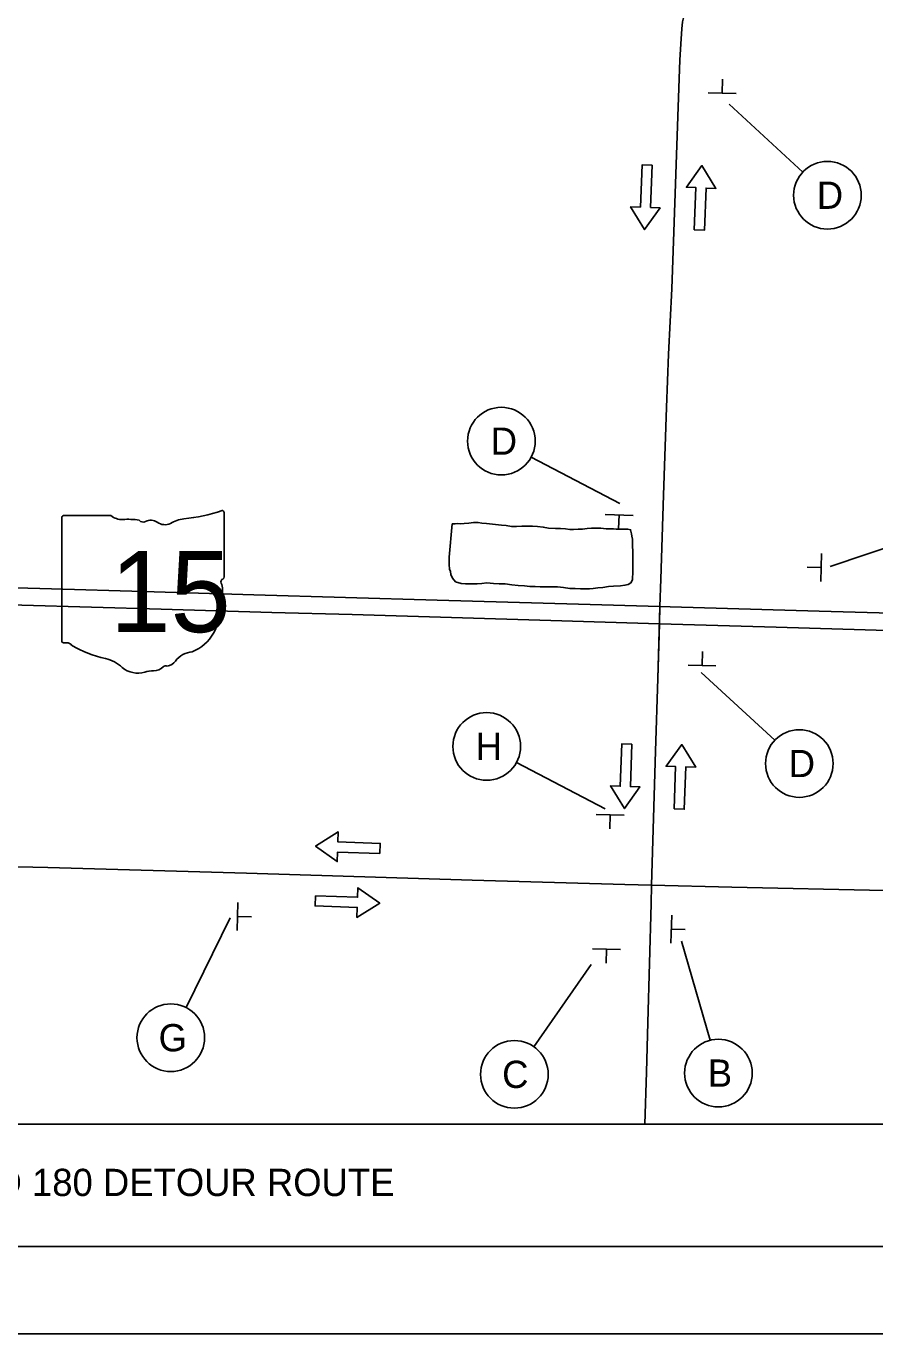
# Model space of a CAD drawing. Extents: x 1651.5 to 1685.5, y 1084.6 to 1106.6.
# Drawn here: x 1660.95 to 1665.81, y 1084.6 to 1092.09 of the extents above; entities that cross this region are included whole.
import ezdxf

# ---------------------------------------------------------------- set-up
doc = ezdxf.new("R2010")
doc.units = 0
for name, color, linetype in [('GM_X_County_Road', 7, 'Continuous'), ('GM_X_Minor_Lake', 7, 'Continuous'), ('GM_X_State_Route', 7, 'Continuous'), ('GM_X_State_Shield', 7, 'Continuous'), ('SC_Scratch1', 7, 'Continuous'), ('SH_Border', 7, 'Continuous'), ('SH_Data', 7, 'Continuous'), ('SH_Text', 7, 'Continuous'), ('SN_P_Signs', 7, 'Continuous')]:
    doc.layers.add(name, color=color, linetype=linetype)

msp = doc.modelspace()

# ---------------------------------------------------------------- linework, layer by layer
at = {"layer": 'GM_X_County_Road'}
for points in [[(1664.5833, 1088.7638), (1664.5876, 1088.9203), (1664.6035, 1089.4012), (1664.6207, 1089.904), (1664.6327, 1090.2091), (1664.6503, 1090.5818), (1664.6617, 1090.9095), (1664.6847, 1091.5685), (1664.6969, 1091.8932), (1664.7038, 1092.014), (1664.7085, 1092.0716), (1664.7131, 1092.1103), (1664.7212, 1092.1486), (1664.7305, 1092.1687), (1664.7444, 1092.1954), (1664.7575, 1092.2144), (1664.7781, 1092.2384)], [(1664.5805, 1088.6652), (1664.5833, 1088.7638)], [(1664.5355, 1087.1696), (1664.5571, 1087.9363), (1664.5718, 1088.3517), (1664.5805, 1088.6652)], [(1657.379, 1087.3642), (1657.4053, 1087.3633), (1657.8544, 1087.3482), (1658.3449, 1087.3387), (1659.8761, 1087.2977), (1661.0794, 1087.2696), (1662.2169, 1087.2377), (1663.5074, 1087.1976), (1664.3823, 1087.1736), (1664.5355, 1087.1696)], [(1664.497, 1085.8005), (1664.5054, 1086.0994), (1664.5145, 1086.3836), (1664.5322, 1087.0616), (1664.5355, 1087.1696)], [(1664.5355, 1087.1696), (1664.9949, 1087.1576), (1665.8697, 1087.1385), (1666.329, 1087.1234), (1667.2696, 1087.0978), (1667.7725, 1087.0776), (1667.9694, 1087.0752), (1668.3411, 1087.089), (1668.5599, 1087.0865), (1668.6882, 1087.0829)]]:
    msp.add_lwpolyline(points, dxfattribs=at)
at = {"layer": 'GM_X_Minor_Lake'}
for points in [[(1663.393, 1089.2365), (1663.3984, 1089.2365), (1663.4091, 1089.2365), (1663.4225, 1089.2391), (1663.4412, 1089.2364), (1663.4626, 1089.239), (1663.4894, 1089.2416), (1663.5161, 1089.2442), (1663.5429, 1089.2441), (1663.5643, 1089.2413), (1663.591, 1089.2386), (1663.6766, 1089.2303), (1663.7034, 1089.2275), (1663.7328, 1089.2221), (1663.7623, 1089.222), (1663.7917, 1089.2246), (1663.8238, 1089.2245), (1663.8532, 1089.2244), (1663.8827, 1089.2216), (1663.9148, 1089.2188), (1663.9442, 1089.2134), (1663.9843, 1089.2106), (1664.0137, 1089.2105), (1664.0432, 1089.2077), (1664.0673, 1089.2049), (1664.0887, 1089.2049), (1664.1154, 1089.2075), (1664.1395, 1089.2074), (1664.1663, 1089.21), (1664.1904, 1089.2126), (1664.2144, 1089.2125), (1664.2439, 1089.2124), (1664.276, 1089.2096), (1664.2974, 1089.2096), (1664.3161, 1089.2095), (1664.3322, 1089.2068), (1664.3482, 1089.2067), (1664.3669, 1089.2067), (1664.3857, 1089.2066), (1664.3991, 1089.2066), (1664.4151, 1089.2038), (1664.4204, 1089.1797), (1664.423, 1089.1664), (1664.4257, 1089.1503), (1664.4256, 1089.1289), (1664.4256, 1089.1075), (1664.4282, 1089.0834), (1664.4282, 1089.0673), (1664.4281, 1089.0486), (1664.4281, 1089.0326), (1664.428, 1089.0138), (1664.428, 1088.9978), (1664.4279, 1088.9523), (1664.4252, 1088.9309), (1664.4251, 1088.9175), (1664.4171, 1088.8988), (1664.401, 1088.8909), (1664.3823, 1088.8856), (1664.3582, 1088.883), (1664.318, 1088.8804), (1664.2886, 1088.8778), (1664.2565, 1088.8726), (1664.227, 1088.87), (1664.2003, 1088.8674), (1664.1789, 1088.8648), (1664.1548, 1088.8649), (1664.128, 1088.865), (1664.0986, 1088.8677), (1664.0665, 1088.8679), (1664.0317, 1088.8733), (1663.9969, 1088.8761), (1663.9541, 1088.8762), (1663.9247, 1088.8763), (1663.8979, 1088.8764), (1663.8685, 1088.8792), (1663.8391, 1088.8793), (1663.807, 1088.8821), (1663.7722, 1088.8848), (1663.7347, 1088.8876), (1663.6973, 1088.8931), (1663.6625, 1088.8932), (1663.6304, 1088.896), (1663.5929, 1088.8988), (1663.5635, 1088.8962), (1663.5367, 1088.8936), (1663.518, 1088.8937), (1663.4993, 1088.8937), (1663.4832, 1088.8938), (1663.4698, 1088.8938), (1663.4458, 1088.8966), (1663.4137, 1088.9047), (1663.395, 1088.9262), (1663.387, 1088.9476), (1663.3844, 1088.9637), (1663.3791, 1088.9771), (1663.3764, 1089.0038), (1663.3765, 1089.0466), (1663.393, 1089.2365)], [(1663.393, 1089.2365), (1663.3765, 1089.0466), (1663.3764, 1089.0038), (1663.3791, 1088.9771), (1663.3844, 1088.9637), (1663.387, 1088.9476), (1663.395, 1088.9262), (1663.4137, 1088.9047), (1663.4458, 1088.8966), (1663.4698, 1088.8938), (1663.4832, 1088.8938), (1663.4993, 1088.8937), (1663.518, 1088.8937), (1663.5367, 1088.8936), (1663.5635, 1088.8962), (1663.5929, 1088.8988), (1663.6304, 1088.896), (1663.6625, 1088.8932), (1663.6973, 1088.8931), (1663.7347, 1088.8876), (1663.7722, 1088.8848), (1663.807, 1088.8821), (1663.8391, 1088.8793), (1663.8685, 1088.8792), (1663.8979, 1088.8764), (1663.9247, 1088.8763), (1663.9541, 1088.8762), (1663.9969, 1088.8761), (1664.0317, 1088.8733), (1664.0665, 1088.8679), (1664.0986, 1088.8677), (1664.128, 1088.865), (1664.1548, 1088.8649), (1664.1789, 1088.8648), (1664.2003, 1088.8674), (1664.227, 1088.87), (1664.2565, 1088.8726), (1664.2886, 1088.8778), (1664.318, 1088.8804), (1664.3582, 1088.883), (1664.3823, 1088.8856), (1664.401, 1088.8909), (1664.4171, 1088.8988), (1664.4251, 1088.9175), (1664.4252, 1088.9309), (1664.4279, 1088.9523), (1664.428, 1088.9978), (1664.428, 1089.0138), (1664.4281, 1089.0326), (1664.4281, 1089.0486)], [(1664.4281, 1089.0486), (1664.4282, 1089.0673), (1664.4282, 1089.0834), (1664.4256, 1089.1075), (1664.4256, 1089.1289), (1664.4257, 1089.1503), (1664.423, 1089.1664), (1664.4204, 1089.1797), (1664.4151, 1089.2038), (1664.3991, 1089.2066), (1664.3857, 1089.2066), (1664.3669, 1089.2067), (1664.3482, 1089.2067), (1664.3322, 1089.2068), (1664.3161, 1089.2095), (1664.2974, 1089.2096), (1664.276, 1089.2096), (1664.2439, 1089.2124), (1664.2144, 1089.2125), (1664.1904, 1089.2126), (1664.1663, 1089.21), (1664.1395, 1089.2074), (1664.1154, 1089.2075), (1664.0887, 1089.2049), (1664.0673, 1089.2049), (1664.0432, 1089.2077), (1664.0137, 1089.2105), (1663.9843, 1089.2106), (1663.9442, 1089.2134), (1663.9148, 1089.2188), (1663.8827, 1089.2216), (1663.8532, 1089.2244), (1663.8238, 1089.2245), (1663.7917, 1089.2246), (1663.7623, 1089.222), (1663.7328, 1089.2221), (1663.7034, 1089.2275), (1663.6766, 1089.2303), (1663.591, 1089.2386), (1663.5643, 1089.2413), (1663.5429, 1089.2441), (1663.5161, 1089.2442), (1663.4894, 1089.2416), (1663.4626, 1089.239), (1663.4412, 1089.2364), (1663.4225, 1089.2391), (1663.4091, 1089.2365), (1663.3984, 1089.2365), (1663.393, 1089.2365)]]:
    msp.add_lwpolyline(points, dxfattribs=at)
at = {"layer": 'GM_X_State_Route'}
for points in [[(1653.9882, 1089.0716), (1654.5206, 1089.0563), (1655.2182, 1089.0358), (1655.7006, 1089.0196), (1656.1829, 1089.0075), (1657.0775, 1088.9829), (1657.4657, 1088.9713), (1658.3454, 1088.9451), (1660.4221, 1088.8844), (1661.0999, 1088.8659), (1661.6244, 1088.8494), (1662.2585, 1088.8312), (1663.3078, 1088.8007), (1664.1166, 1088.777), (1664.5833, 1088.7638), (1664.6413, 1088.7624), (1665.4938, 1088.737), (1665.9748, 1088.7239), (1666.6305, 1088.7038), (1667.0677, 1088.6901), (1668.268, 1088.6514), (1668.4116, 1088.6492), (1668.6882, 1088.6439)], [(1653.9882, 1088.972), (1654.9177, 1088.9448), (1655.9668, 1088.9137), (1656.6661, 1088.8935), (1657.4608, 1088.8688), (1658.0564, 1088.8506), (1658.4943, 1088.8393), (1659.3219, 1088.8187), (1660.1311, 1088.7948), (1661.7276, 1088.748), (1662.3619, 1088.7295), (1662.8212, 1088.7178), (1663.9585, 1088.6833), (1664.5805, 1088.6652), (1665.2488, 1088.6454), (1666.6484, 1088.6041), (1667.6764, 1088.5732), (1668.5696, 1088.5488), (1668.6882, 1088.5445)]]:
    msp.add_lwpolyline(points, dxfattribs=at)
at = {"layer": 'GM_X_State_Shield'}
for p, q in [((1662.0878, 1088.9332), (1662.0878, 1089.3017)), ((1661.1597, 1089.2721), (1661.1597, 1088.5677)), ((1661.4406, 1089.2842), (1661.1688, 1089.2842)), ((1662.0877, 1088.9333), (1662.0878, 1088.9332))]:
    msp.add_line(p, q, dxfattribs=at)
for centre, radius, start, end in [((1661.7572, 1090.2446), 0.9842, 275.84447, 288.90645), ((1662.0775, 1089.3032), 0.0103, 351.86209, 97.738), ((1661.1703, 1089.2736), 0.0108, 98.1301, 188.1301), ((1661.5053, 1089.366), 0.1043, 231.61951, 271.11188), ((1661.5399, 1088.8888), 0.3744, 80.48669, 94.98827), ((1661.6249, 1089.2773), 0.0301, 219.79206, 297.10237), ((1661.6691, 1089.1958), 0.0626, 54.46668, 119.14113), ((1661.7498, 1089.3075), 0.0753, 233.85621, 294.82819), ((1661.8827, 1089.0691), 0.198, 97.34618, 120.76885), ((1662.0767, 1088.9318), 0.0111, 289.60381, 7.73413), ((1662.0854, 1088.9061), 0.016, 107.94398, 210.33697), ((1661.9837, 1088.8596), 0.096, 340.03296, 23.64957), ((1662.1248, 1088.779), 0.0698, 136.8065, 186.92959), ((1661.8123, 1088.7321), 0.2462, 292.30889, 8.98584), ((1661.1704, 1088.5661), 0.0108, 171.95839, 258.30661), ((1661.172, 1088.6382), 0.0828, 267.33899, 280.60386), ((1661.189, 1088.527), 0.0298, 29.74838, 93.27175), ((1661.5658, 1089.1599), 0.7108, 240.41292, 257.1985), ((1661.9161, 1088.3699), 0.1348, 94.40312, 142.57675), ((1661.3539, 1088.2512), 0.2224, 47.18416, 75.83597), ((1661.5944, 1088.5236), 0.1411, 230.70037, 286.29184), ((1661.6863, 1088.4708), 0.0752, 268.77702, 315.54927), ((1661.7543, 1088.4026), 0.0212, 65.75173, 132.64842), ((1661.7453, 1088.4994), 0.0795, 282.87319, 323.27711), ((1661.676, 1088.28), 0.116, 85.69512, 111.20995)]:
    msp.add_arc(centre, radius, start, end, dxfattribs=at)
at = {"layer": 'SC_Scratch1'}
msp.add_lwpolyline([(1651.4632, 1106.6005), (1685.4632, 1106.6005), (1685.4632, 1084.6005), (1651.4632, 1084.6005)], close=True, dxfattribs=at)
at = {"layer": 'SH_Border'}
msp.add_lwpolyline([(1651.9632, 1106.1005), (1684.9632, 1106.1005), (1684.9632, 1085.1005), (1651.9632, 1085.1005)], close=True, dxfattribs=at)
at = {"layer": 'SH_Data'}
msp.add_lwpolyline([(1653.9882, 1105.4005), (1668.6882, 1105.4005), (1668.6882, 1085.8005), (1653.9882, 1085.8005)], close=True, dxfattribs=at)
at = {"layer": 'SH_Text'}
for p, q in [((1664.9798, 1091.6395), (1665.401, 1091.2512)), ((1664.4718, 1091.0502), (1664.4807, 1091.2921)), ((1664.4807, 1091.2921), (1664.5387, 1091.29)), ((1664.5297, 1091.0481), (1664.5387, 1091.29)), ((1664.8237, 1091.288), (1664.7343, 1091.1637)), ((1664.8237, 1091.288), (1664.9038, 1091.1575)), ((1664.7343, 1091.1637), (1664.7888, 1091.1617)), ((1664.7888, 1091.1617), (1664.7799, 1090.9198)), ((1664.8468, 1091.1596), (1664.8379, 1090.9177)), ((1664.9038, 1091.1575), (1664.8468, 1091.1596)), ((1664.4948, 1090.9218), (1664.4148, 1091.0523)), ((1664.4148, 1091.0523), (1664.4718, 1091.0502)), ((1664.4948, 1090.9218), (1664.5843, 1091.0461)), ((1664.5843, 1091.0461), (1664.5297, 1091.0481)), ((1664.8379, 1090.9177), (1664.7799, 1090.9198)), ((1664.3533, 1089.3529), (1663.8458, 1089.6187)), ((1665.5576, 1088.9926), (1666.1003, 1089.1761)), ((1664.819, 1088.3862), (1665.2403, 1087.998)), ((1664.3563, 1087.7354), (1664.3647, 1087.9772)), ((1664.3647, 1087.9772), (1664.4227, 1087.9752)), ((1664.4143, 1087.7333), (1664.4227, 1087.9752)), ((1664.7078, 1087.9739), (1664.6186, 1087.8494)), ((1664.7078, 1087.9739), (1664.7881, 1087.8435)), ((1664.2693, 1087.6054), (1663.7618, 1087.8712)), ((1664.6186, 1087.8494), (1664.6731, 1087.8475)), ((1664.6731, 1087.8475), (1664.6647, 1087.6056)), ((1664.7311, 1087.8455), (1664.7227, 1087.6036)), ((1664.7881, 1087.8435), (1664.7311, 1087.8455)), ((1664.3796, 1087.607), (1664.2993, 1087.7373)), ((1664.2993, 1087.7373), (1664.3563, 1087.7354)), ((1664.3796, 1087.607), (1664.4688, 1087.7314)), ((1664.4688, 1087.7314), (1664.4143, 1087.7333)), ((1664.7227, 1087.6036), (1664.6647, 1087.6056)), ((1662.6114, 1087.3928), (1662.7416, 1087.4733)), ((1662.7416, 1087.4733), (1662.7397, 1087.4163)), ((1662.6114, 1087.3928), (1662.736, 1087.3038)), ((1662.736, 1087.3038), (1662.7378, 1087.3583)), ((1662.7378, 1087.3583), (1662.9797, 1087.3503)), ((1662.7397, 1087.4163), (1662.9816, 1087.4083)), ((1662.9816, 1087.4083), (1662.9797, 1087.3503)), ((1662.8542, 1087.1542), (1662.8524, 1087.0996)), ((1662.9788, 1087.0652), (1662.8542, 1087.1542)), ((1662.6085, 1087.0497), (1662.6105, 1087.1077)), ((1662.8524, 1087.0996), (1662.6105, 1087.1077)), ((1662.9788, 1087.0652), (1662.8486, 1086.9847)), ((1662.1237, 1086.9822), (1661.8706, 1086.4683)), ((1662.8504, 1087.0417), (1662.6085, 1087.0497)), ((1662.8486, 1086.9847), (1662.8504, 1087.0417)), ((1664.7071, 1086.8482), (1664.8701, 1086.2807)), ((1664.189, 1086.7141), (1663.862, 1086.2437))]:
    msp.add_line(p, q, dxfattribs=at)
for points in [[(1664.5833, 1088.7638), (1664.5876, 1088.9203), (1664.6035, 1089.4012), (1664.6207, 1089.904), (1664.6327, 1090.2091), (1664.6503, 1090.5818), (1664.6617, 1090.9095), (1664.6847, 1091.5685), (1664.6969, 1091.8932), (1664.7038, 1092.014), (1664.7085, 1092.0716), (1664.7131, 1092.1103), (1664.7212, 1092.1486), (1664.7305, 1092.1687), (1664.7444, 1092.1954), (1664.7575, 1092.2144), (1664.7781, 1092.2384)], [(1664.5355, 1087.1696), (1664.5571, 1087.9363), (1664.5718, 1088.3517), (1664.5833, 1088.7638)], [(1657.379, 1087.3642), (1657.4053, 1087.3633), (1657.8544, 1087.3482), (1658.3449, 1087.3387), (1659.8761, 1087.2977), (1661.0794, 1087.2696), (1662.2169, 1087.2377), (1663.5074, 1087.1976), (1664.3823, 1087.1736), (1664.5355, 1087.1696)]]:
    msp.add_lwpolyline(points, dxfattribs=at)
for points in [[(1664.5387, 1091.29), (1664.5297, 1091.0481), (1664.5843, 1091.0461), (1664.4948, 1090.9218), (1664.4148, 1091.0523), (1664.4718, 1091.0502), (1664.4807, 1091.2921)], [(1664.7799, 1090.9198), (1664.7888, 1091.1617), (1664.7343, 1091.1637), (1664.8237, 1091.288), (1664.9038, 1091.1575), (1664.8468, 1091.1596), (1664.8379, 1090.9177)], [(1664.4227, 1087.9752), (1664.4143, 1087.7333), (1664.4688, 1087.7314), (1664.3797, 1087.607), (1664.2993, 1087.7373), (1664.3563, 1087.7354), (1664.3647, 1087.9772)], [(1664.6647, 1087.6056), (1664.6731, 1087.8475), (1664.6186, 1087.8494), (1664.7078, 1087.9739), (1664.7881, 1087.8435), (1664.7311, 1087.8455), (1664.7227, 1087.6036)], [(1662.9797, 1087.3503), (1662.7378, 1087.3583), (1662.736, 1087.3038), (1662.6114, 1087.3928), (1662.7416, 1087.4733), (1662.7397, 1087.4163), (1662.9816, 1087.4083)], [(1662.6105, 1087.1077), (1662.8524, 1087.0996), (1662.8542, 1087.1542), (1662.9788, 1087.0652), (1662.8486, 1086.9847), (1662.8505, 1087.0417), (1662.6086, 1087.0497)]]:
    msp.add_lwpolyline(points, close=True, dxfattribs=at)
for centre in [(1665.5419, 1091.1184), (1663.6754, 1089.7106), (1663.5914, 1087.963), (1665.3811, 1087.8652), (1661.783, 1086.2957), (1663.7497, 1086.086), (1664.9178, 1086.093)]:
    msp.add_circle(centre, 0.1936, dxfattribs=at)
at = {"layer": 'SN_P_Signs'}
for p, q in [((1664.9399, 1091.7028), (1664.942, 1091.7828)), ((1664.86, 1091.7049), (1665.0199, 1091.7007)), ((1664.4289, 1089.2858), (1664.2689, 1089.29)), ((1664.3489, 1089.2879), (1664.3468, 1089.2079)), ((1665.5036, 1088.9068), (1665.5083, 1089.0667)), ((1665.5059, 1088.9867), (1665.426, 1088.9891)), ((1664.824, 1088.4264), (1664.8261, 1088.5064)), ((1664.744, 1088.4285), (1664.904, 1088.4244)), ((1664.3775, 1087.5696), (1664.2176, 1087.5738)), ((1664.2975, 1087.5717), (1664.2955, 1087.4917)), ((1662.1674, 1087.0691), (1662.1627, 1086.9092)), ((1662.165, 1086.9891), (1662.245, 1086.9868)), ((1664.6505, 1086.9965), (1664.6458, 1086.8366)), ((1664.6482, 1086.9166), (1664.7281, 1086.9142)), ((1664.3569, 1086.8011), (1664.197, 1086.8053)), ((1664.2769, 1086.8032), (1664.2749, 1086.7232))]:
    msp.add_line(p, q, dxfattribs=at)

# ---------------------------------------------------------------- texts
at = {"layer": 'GM_X_State_Shield'}
msp.add_text('15', height=0.46406, dxfattribs=at).set_placement((1661.436, 1088.6174))
at = {"layer": 'SH_Text'}
for s, p in [('D', (1665.4811, 1091.0404)), ('D', (1663.6146, 1089.6326)), ('H', (1663.5281, 1087.885)), ('D', (1665.3203, 1087.7872)), ('G', (1661.713, 1086.2177)), ('C', (1663.6797, 1086.008)), ('B', (1664.857, 1086.015)), ('COUNTY ROAD 180 DETOUR ROUTE', (1659.389, 1085.3894))]:
    msp.add_text(s, height=0.156, dxfattribs=at).set_placement(p)

doc.saveas('drawing.dxf')
